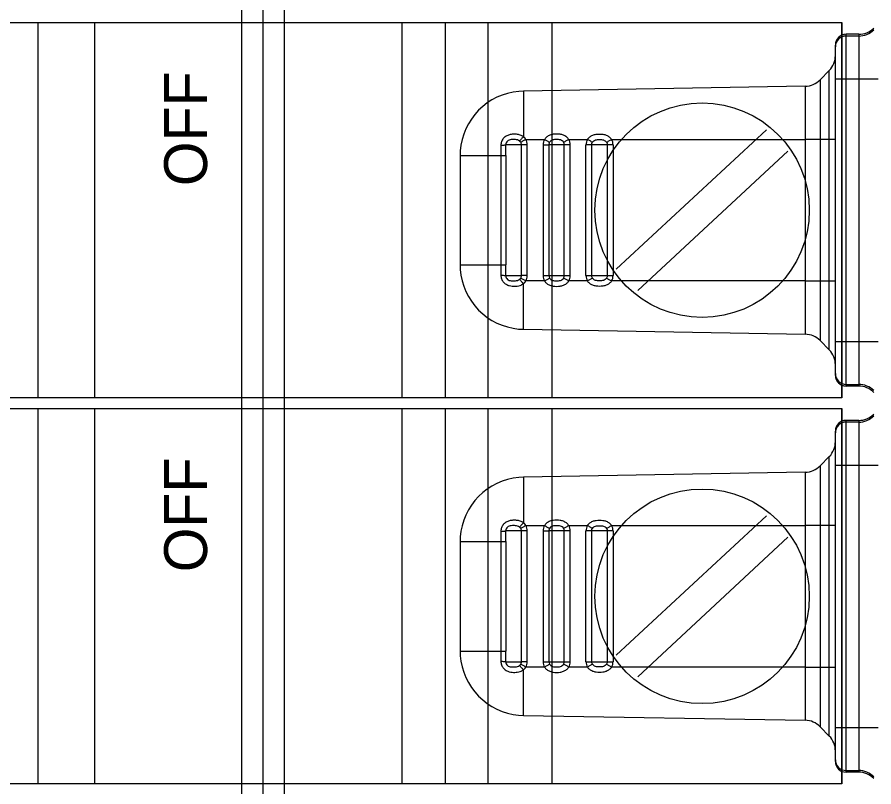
# Model space of a CAD drawing. Extents: x 0 to 4205, y 0 to 2970.
# Drawn here: x 958.55 to 998.5, y 1101.46 to 1137.34 of the extents above; entities that cross this region are included whole.
import ezdxf

# ---------------------------------------------------------------- set-up
doc = ezdxf.new("R2010")
doc.units = 0
doc.layers.add('Level 1', color=7, linetype='Continuous')

# ---------------------------------------------------------------- blocks, each defined once
blk = doc.blocks.new('NCX-2418-3U')
for p, q in [((-178, 132.85), (-178, -99.15)), ((-177, 132.85), (-177, -99.15)), ((-176, 132.85), (-176, -99.15)), ((-149.8, 53.451), (-149.8, 69.849)), ((-149.214, 69.849), (-149.8, 69.849)), ((-149.214, 69.849), (-149.8, 69.849)), ((-149.214, 69.77), (-149.8, 69.77)), ((-149.214, 69.849), (-149.214, 53.451)), ((-150.3, 53.951), (-150.3, 69.349)), ((-150.587, 68.164), (-151.013, 67.73)), ((-150.587, 55.136), (-150.587, 68.164)), ((-151.013, 67.73), (-151.013, 55.57)), ((-150.3, 67.771), (-148.3, 67.771)), ((-151.709, 67.431), (-164.852, 67.201)), ((-164.852, 67.201), (-164.852, 65.074)), ((-151.709, 67.431), (-151.709, 64.95)), ((-164.735, 64.95), (-163.865, 64.95)), ((-162.735, 64.95), (-161.865, 64.95)), ((-160.735, 64.95), (-151.709, 64.95)), ((-151.709, 64.95), (-151.709, 55.869)), ((-150.3, 64.95), (-151.709, 64.95)), ((-164.668, 64.7), (-165.674, 64.7)), ((-164.942, 58.6), (-164.942, 64.7)), ((-164.668, 58.6), (-164.668, 64.7)), ((-163.932, 64.7), (-163.932, 58.6)), ((-163.932, 64.7), (-163.664, 64.7)), ((-163.664, 64.7), (-163.664, 58.6)), ((-162.942, 64.7), (-163.664, 64.7)), ((-162.942, 58.6), (-162.942, 64.7)), ((-162.668, 64.7), (-162.942, 64.7)), ((-162.668, 58.6), (-162.668, 64.7)), ((-161.932, 58.6), (-161.932, 64.7)), ((-160.668, 64.7), (-161.932, 64.7)), ((-161.664, 58.6), (-161.664, 64.7)), ((-160.942, 64.7), (-160.942, 58.6)), ((-160.668, 64.7), (-160.668, 58.6)), ((-167.8, 64.202), (-167.8, 59.098)), ((-167.8, 64.202), (-165.67, 64.202)), ((-165.902, 64.202), (-165.902, 59.098)), ((-165.67, 64.202), (-165.67, 59.098)), ((-167.8, 59.098), (-165.902, 59.098)), ((-165.902, 59.098), (-165.67, 59.098)), ((-165.674, 58.6), (-164.942, 58.6)), ((-164.668, 58.6), (-164.942, 58.6)), ((-163.865, 58.35), (-164.735, 58.35)), ((-163.932, 58.6), (-162.668, 58.6)), ((-161.865, 58.35), (-162.735, 58.35)), ((-161.932, 58.6), (-160.668, 58.6)), ((-151.709, 58.35), (-160.735, 58.35)), ((-151.709, 58.35), (-150.3, 58.35)), ((-164.852, 56.099), (-164.852, 58.225)), ((-164.852, 56.099), (-151.709, 55.869)), ((-151.013, 55.57), (-150.587, 55.136)), ((-150.3, 55.529), (-148.3, 55.529)), ((-149.8, 53.53), (-149.214, 53.53)), ((-149.214, 53.451), (-149.8, 53.451)), ((-149.214, 53.451), (-149.8, 53.451)), ((-149.8, 35.451), (-149.8, 51.849)), ((-149.214, 51.849), (-149.8, 51.849)), ((-149.214, 51.849), (-149.8, 51.849)), ((-149.214, 51.77), (-149.8, 51.77)), ((-149.214, 51.849), (-149.214, 35.451)), ((-150.3, 35.951), (-150.3, 51.349)), ((-150.587, 50.164), (-151.013, 49.73)), ((-150.587, 37.136), (-150.587, 50.164)), ((-151.013, 49.73), (-151.013, 37.57)), ((-150.3, 49.771), (-148.3, 49.771)), ((-151.709, 49.431), (-164.852, 49.201)), ((-164.852, 49.201), (-164.852, 47.074)), ((-151.709, 49.431), (-151.709, 37.869)), ((-164.735, 46.95), (-163.865, 46.95)), ((-162.735, 46.95), (-161.865, 46.95)), ((-160.735, 46.95), (-151.709, 46.95)), ((-150.3, 46.95), (-151.709, 46.95)), ((-164.668, 46.7), (-165.674, 46.7)), ((-164.942, 40.6), (-164.942, 46.7)), ((-164.668, 40.6), (-164.668, 46.7)), ((-163.932, 46.7), (-163.932, 40.6)), ((-163.932, 46.7), (-163.664, 46.7)), ((-163.664, 46.7), (-163.664, 40.6)), ((-162.942, 46.7), (-163.664, 46.7)), ((-162.942, 40.6), (-162.942, 46.7)), ((-162.668, 46.7), (-162.942, 46.7)), ((-162.668, 40.6), (-162.668, 46.7)), ((-161.932, 40.6), (-161.932, 46.7)), ((-160.668, 46.7), (-161.932, 46.7)), ((-161.664, 40.6), (-161.664, 46.7)), ((-160.942, 46.7), (-160.942, 40.6)), ((-160.668, 46.7), (-160.668, 40.6)), ((-167.8, 46.202), (-167.8, 41.098)), ((-167.8, 46.202), (-165.67, 46.202)), ((-165.902, 46.202), (-165.902, 41.098)), ((-165.67, 46.202), (-165.67, 41.098)), ((-167.8, 41.098), (-165.902, 41.098)), ((-165.902, 41.098), (-165.67, 41.098)), ((-165.674, 40.6), (-164.942, 40.6)), ((-164.668, 40.6), (-164.942, 40.6)), ((-163.932, 40.6), (-162.668, 40.6)), ((-161.932, 40.6), (-160.668, 40.6)), ((-151.709, 40.35), (-150.3, 40.35)), ((-164.852, 38.099), (-164.852, 40.225)), ((-163.865, 40.35), (-164.735, 40.35)), ((-161.865, 40.35), (-162.735, 40.35)), ((-151.709, 40.35), (-160.735, 40.35)), ((-164.852, 38.099), (-151.709, 37.869)), ((-151.013, 37.57), (-150.587, 37.136)), ((-150.3, 37.529), (-148.3, 37.529)), ((-149.8, 35.53), (-149.214, 35.53)), ((-149.214, 35.451), (-149.8, 35.451)), ((-149.214, 35.451), (-149.8, 35.451))]:
    blk.add_line(p, q)
for points in [[(-164.852, 67.201), (-165.07, 67.19), (-165.331, 67.155), (-165.588, 67.096), (-165.84, 67.016), (-166.083, 66.914), (-166.316, 66.791), (-166.537, 66.648), (-166.746, 66.486), (-166.939, 66.306), (-167.115, 66.11), (-167.274, 65.899), (-167.413, 65.676), (-167.532, 65.44), (-167.631, 65.196), (-167.707, 64.943), (-167.761, 64.685), (-167.792, 64.423), (-167.8, 64.202)], [(-167.8, 59.098), (-167.792, 58.88), (-167.761, 58.619), (-167.708, 58.36), (-167.632, 58.108), (-167.534, 57.863), (-167.415, 57.628), (-167.276, 57.404), (-167.117, 57.193), (-166.941, 56.997), (-166.748, 56.817), (-166.541, 56.655), (-166.319, 56.511), (-166.086, 56.388), (-165.843, 56.285), (-165.592, 56.205), (-165.335, 56.146), (-165.073, 56.111), (-164.852, 56.099)], [(-164.852, 49.201), (-165.07, 49.19), (-165.331, 49.155), (-165.588, 49.096), (-165.84, 49.016), (-166.083, 48.914), (-166.316, 48.791), (-166.537, 48.648), (-166.746, 48.486), (-166.939, 48.306), (-167.115, 48.11), (-167.274, 47.899), (-167.413, 47.676), (-167.532, 47.44), (-167.631, 47.196), (-167.707, 46.943), (-167.761, 46.685), (-167.792, 46.423), (-167.8, 46.202)], [(-167.8, 41.098), (-167.792, 40.88), (-167.761, 40.619), (-167.708, 40.36), (-167.632, 40.108), (-167.534, 39.863), (-167.415, 39.628), (-167.276, 39.404), (-167.117, 39.193), (-166.941, 38.997), (-166.748, 38.817), (-166.541, 38.655), (-166.319, 38.511), (-166.086, 38.388), (-165.843, 38.285), (-165.592, 38.205), (-165.335, 38.146), (-165.073, 38.111), (-164.852, 38.099)]]:
    blk.add_lwpolyline(points)
for centre, radius, start, end in [((-149.214, 70.849), 1, 270, 315), ((-149.214, 70.849), 1, 269.9984, 314.9877), ((-149.214, 70.77), 1, 269.9984, 314.9877), ((-149.8, 69.349), 0.5, 90, 180), ((-149.8, 69.349), 0.5, 89.9895, 179.9895), ((-149.8, 69.27), 0.5, 89.9895, 179.9895), ((-151.3, 68.865), 1, 315.5, 359.9974), ((-151.726, 68.431), 1, 271, 315.4998), ((-165.167, 64.7), 0.499, 0.0299, 30.0713), ((-163.433, 64.7), 0.5, 149.9278, 179.963), ((-163.167, 64.7), 0.5, 0.0336, 30.0749), ((-161.433, 64.7), 0.499, 149.9288, 179.9703), ((-161.167, 64.7), 0.499, 0.0299, 30.0709), ((-194.009, 64.214), 28.339, 359.9754, 0.9825), ((-194.015, 59.086), 28.344, 359.0176, 0.0247), ((-165.167, 58.6), 0.499, 329.9312, 359.969), ((-163.433, 58.6), 0.5, 180.0364, 210.0773), ((-163.447, 58.6), 0.217, 180.0423, 211.5562), ((-163.167, 58.6), 0.499, 329.9303, 359.9687), ((-161.433, 58.6), 0.499, 180.0293, 210.0718), ((-161.167, 58.6), 0.499, 329.9282, 359.9708), ((-151.726, 54.869), 1, 44.5002, 89), ((-151.3, 54.435), 1, 0.0453, 44.5), ((-149.8, 54.03), 0.5, 180.0105, 270.0105), ((-149.8, 53.951), 0.5, 180, 270), ((-149.8, 53.951), 0.5, 180.0105, 270.0105), ((-149.214, 52.53), 1, 45.0123, 90.0016), ((-149.214, 52.451), 1, 45.0123, 90.0016), ((-149.214, 52.451), 1, 45, 90), ((-149.214, 52.849), 1, 270, 315), ((-149.214, 52.849), 1, 269.9984, 314.9877), ((-149.214, 52.77), 1, 269.9984, 314.9877), ((-149.8, 51.349), 0.5, 90, 180), ((-149.8, 51.349), 0.5, 89.9895, 179.9895), ((-149.8, 51.27), 0.5, 89.9895, 179.9895), ((-151.3, 50.865), 1, 315.5, 359.9974), ((-151.726, 50.431), 1, 271, 315.4998), ((-165.167, 46.7), 0.499, 0.0299, 30.0713), ((-163.433, 46.7), 0.5, 149.9278, 179.963), ((-163.167, 46.7), 0.5, 0.0336, 30.0749), ((-161.433, 46.7), 0.499, 149.9288, 179.9703), ((-161.167, 46.7), 0.499, 0.0299, 30.0709), ((-194.009, 46.214), 28.339, 359.9754, 0.9825), ((-194.015, 41.086), 28.344, 359.0176, 0.0247), ((-165.167, 40.6), 0.499, 329.9312, 359.969), ((-163.433, 40.6), 0.5, 180.0364, 210.0773), ((-163.447, 40.6), 0.217, 180.0423, 211.5562), ((-163.167, 40.6), 0.499, 329.9303, 359.9687), ((-161.433, 40.6), 0.499, 180.0293, 210.0718), ((-161.167, 40.6), 0.499, 329.9282, 359.9708), ((-151.726, 36.869), 1, 44.5002, 89), ((-151.3, 36.435), 1, 0.0453, 44.5), ((-149.8, 36.03), 0.5, 180.0105, 270.0105), ((-149.8, 35.951), 0.5, 180, 270), ((-149.8, 35.951), 0.5, 180.0105, 270.0105), ((-149.214, 34.53), 1, 45.0123, 90.0016), ((-149.214, 34.451), 1, 45.0123, 90.0016), ((-149.214, 34.451), 1, 45, 90)]:
    blk.add_arc(centre, radius, start, end)
for points, degree in [([(-164.852, 65.074), (-164.897, 65.109), (-164.998, 65.163), (-165.166, 65.197), (-165.336, 65.197), (-165.504, 65.174), (-165.663, 65.109), (-165.794, 64.997), (-165.88, 64.848), (-165.901, 64.734), (-165.901, 64.678)], 3), ([(-162.735, 64.95), (-162.764, 64.995), (-162.839, 65.075), (-162.981, 65.154), (-163.139, 65.194), (-163.3, 65.204), (-163.461, 65.194), (-163.618, 65.154), (-163.761, 65.075), (-163.836, 64.995), (-163.865, 64.95)], 3), ([(-161.865, 64.95), (-161.836, 64.995), (-161.761, 65.075), (-161.619, 65.155), (-161.461, 65.194), (-161.3, 65.204), (-161.138, 65.194), (-160.981, 65.155), (-160.839, 65.075), (-160.764, 64.995), (-160.735, 64.95)], 3), ([(-165.031, 64.878), (-165.057, 64.898), (-165.119, 64.928), (-165.217, 64.942), (-165.316, 64.945), (-165.414, 64.942), (-165.511, 64.927), (-165.6, 64.881), (-165.662, 64.801), (-165.676, 64.733), (-165.674, 64.7)], 3), ([(-164.852, 65.074), (-164.887, 65.034), (-164.935, 64.978), (-164.996, 64.913), (-165.021, 64.888), (-165.031, 64.878)], 3), ([(-164.974, 64.814), (-164.989, 64.838), (-165.009, 64.86), (-165.031, 64.878)], 2), ([(-164.735, 64.95), (-164.782, 64.923), (-164.861, 64.877), (-164.941, 64.832), (-164.974, 64.814)], 3), ([(-164.942, 64.7), (-164.942, 64.72), (-164.947, 64.76), (-164.964, 64.797), (-164.974, 64.814)], 3), ([(-164.735, 64.95), (-164.766, 64.998), (-164.807, 65.04), (-164.852, 65.074)], 2), ([(-163.865, 64.95), (-163.819, 64.923), (-163.741, 64.878), (-163.663, 64.832), (-163.632, 64.814)], 3), ([(-163.632, 64.814), (-163.643, 64.797), (-163.659, 64.76), (-163.664, 64.72), (-163.664, 64.7)], 3), ([(-162.974, 64.814), (-162.99, 64.84), (-163.033, 64.887), (-163.119, 64.927), (-163.211, 64.941), (-163.304, 64.943), (-163.396, 64.941), (-163.488, 64.927), (-163.573, 64.887), (-163.616, 64.84), (-163.632, 64.814)], 3), ([(-162.735, 64.95), (-162.782, 64.923), (-162.861, 64.877), (-162.941, 64.832), (-162.974, 64.814)], 3), ([(-162.942, 64.7), (-162.942, 64.72), (-162.947, 64.76), (-162.964, 64.797), (-162.974, 64.814)], 3), ([(-161.632, 64.814), (-161.663, 64.832), (-161.741, 64.878), (-161.819, 64.923), (-161.865, 64.95)], 3), ([(-161.664, 64.7), (-161.664, 64.739), (-161.653, 64.78), (-161.632, 64.814)], 2), ([(-161.632, 64.814), (-161.616, 64.84), (-161.573, 64.887), (-161.488, 64.927), (-161.396, 64.941), (-161.304, 64.943), (-161.211, 64.941), (-161.119, 64.927), (-161.033, 64.887), (-160.99, 64.84), (-160.974, 64.814)], 3), ([(-160.974, 64.814), (-160.941, 64.832), (-160.861, 64.877), (-160.782, 64.923), (-160.735, 64.95)], 3), ([(-160.974, 64.814), (-160.964, 64.797), (-160.947, 64.76), (-160.942, 64.72), (-160.942, 64.7)], 3), ([(-165.901, 64.678), (-165.901, 64.519), (-165.902, 64.361), (-165.902, 64.202)], 2), ([(-165.901, 64.678), (-165.854, 64.68), (-165.791, 64.684), (-165.716, 64.692), (-165.686, 64.697), (-165.674, 64.7)], 3), ([(-165.902, 59.098), (-165.902, 58.94), (-165.901, 58.781), (-165.901, 58.622)], 2), ([(-165.901, 58.622), (-165.854, 58.62), (-165.791, 58.616), (-165.716, 58.608), (-165.686, 58.603), (-165.674, 58.6)], 3), ([(-165.901, 58.622), (-165.901, 58.566), (-165.88, 58.452), (-165.794, 58.303), (-165.663, 58.191), (-165.504, 58.126), (-165.364, 58.106), (-165.251, 58.103), (-165.138, 58.109), (-164.998, 58.137), (-164.897, 58.191), (-164.852, 58.225)], 3), ([(-165.674, 58.6), (-165.676, 58.567), (-165.662, 58.499), (-165.6, 58.419), (-165.511, 58.373), (-165.414, 58.358), (-165.316, 58.355), (-165.217, 58.358), (-165.119, 58.372), (-165.058, 58.402), (-165.031, 58.422)], 3), ([(-165.031, 58.422), (-165.009, 58.44), (-164.989, 58.462), (-164.974, 58.486)], 2), ([(-164.852, 58.225), (-164.887, 58.266), (-164.935, 58.322), (-164.996, 58.387), (-165.021, 58.412), (-165.031, 58.422)], 3), ([(-164.974, 58.486), (-164.964, 58.503), (-164.947, 58.54), (-164.942, 58.58), (-164.942, 58.6)], 3), ([(-164.735, 58.35), (-164.782, 58.377), (-164.861, 58.423), (-164.941, 58.468), (-164.974, 58.486)], 3), ([(-164.852, 58.225), (-164.807, 58.26), (-164.766, 58.302), (-164.735, 58.35)], 2), ([(-163.865, 58.35), (-163.819, 58.377), (-163.741, 58.422), (-163.663, 58.468), (-163.632, 58.486)], 3), ([(-163.865, 58.35), (-163.836, 58.305), (-163.761, 58.225), (-163.618, 58.146), (-163.461, 58.106), (-163.3, 58.096), (-163.138, 58.106), (-162.981, 58.146), (-162.839, 58.225), (-162.764, 58.305), (-162.735, 58.35)], 3), ([(-163.632, 58.486), (-163.616, 58.46), (-163.573, 58.413), (-163.488, 58.373), (-163.396, 58.359), (-163.304, 58.357), (-163.211, 58.359), (-163.119, 58.373), (-163.033, 58.413), (-162.99, 58.46), (-162.974, 58.486)], 3), ([(-162.974, 58.486), (-162.964, 58.503), (-162.947, 58.54), (-162.942, 58.58), (-162.942, 58.6)], 3), ([(-162.735, 58.35), (-162.782, 58.377), (-162.861, 58.423), (-162.941, 58.468), (-162.974, 58.486)], 3), ([(-161.632, 58.486), (-161.663, 58.468), (-161.741, 58.422), (-161.819, 58.377), (-161.865, 58.35)], 3), ([(-160.735, 58.35), (-160.764, 58.305), (-160.839, 58.225), (-160.981, 58.145), (-161.138, 58.106), (-161.3, 58.096), (-161.461, 58.106), (-161.619, 58.145), (-161.761, 58.225), (-161.836, 58.305), (-161.865, 58.35)], 3), ([(-161.632, 58.486), (-161.643, 58.503), (-161.659, 58.54), (-161.664, 58.58), (-161.664, 58.6)], 3), ([(-160.974, 58.486), (-160.99, 58.46), (-161.033, 58.413), (-161.119, 58.373), (-161.211, 58.359), (-161.304, 58.357), (-161.396, 58.359), (-161.488, 58.373), (-161.573, 58.413), (-161.616, 58.46), (-161.632, 58.486)], 3), ([(-160.942, 58.6), (-160.942, 58.58), (-160.947, 58.54), (-160.964, 58.503), (-160.974, 58.486)], 3), ([(-160.974, 58.486), (-160.941, 58.468), (-160.861, 58.423), (-160.782, 58.377), (-160.735, 58.35)], 3), ([(-164.852, 47.074), (-164.897, 47.109), (-164.998, 47.163), (-165.166, 47.197), (-165.336, 47.197), (-165.504, 47.174), (-165.663, 47.109), (-165.794, 46.997), (-165.88, 46.848), (-165.901, 46.734), (-165.901, 46.678)], 3), ([(-162.735, 46.95), (-162.764, 46.995), (-162.839, 47.075), (-162.981, 47.154), (-163.139, 47.194), (-163.3, 47.204), (-163.461, 47.194), (-163.618, 47.154), (-163.761, 47.075), (-163.836, 46.995), (-163.865, 46.95)], 3), ([(-161.865, 46.95), (-161.836, 46.995), (-161.761, 47.075), (-161.619, 47.155), (-161.461, 47.194), (-161.3, 47.204), (-161.138, 47.194), (-160.981, 47.155), (-160.839, 47.075), (-160.764, 46.995), (-160.735, 46.95)], 3), ([(-165.031, 46.878), (-165.057, 46.898), (-165.119, 46.928), (-165.217, 46.942), (-165.316, 46.945), (-165.414, 46.942), (-165.511, 46.927), (-165.6, 46.881), (-165.662, 46.801), (-165.676, 46.733), (-165.674, 46.7)], 3), ([(-164.852, 47.074), (-164.887, 47.034), (-164.935, 46.978), (-164.996, 46.913), (-165.021, 46.888), (-165.031, 46.878)], 3), ([(-164.974, 46.814), (-164.989, 46.838), (-165.009, 46.86), (-165.031, 46.878)], 2), ([(-164.735, 46.95), (-164.782, 46.923), (-164.861, 46.877), (-164.941, 46.832), (-164.974, 46.814)], 3), ([(-164.942, 46.7), (-164.942, 46.72), (-164.947, 46.76), (-164.964, 46.797), (-164.974, 46.814)], 3), ([(-164.735, 46.95), (-164.766, 46.998), (-164.807, 47.04), (-164.852, 47.074)], 2), ([(-163.865, 46.95), (-163.819, 46.923), (-163.741, 46.878), (-163.663, 46.832), (-163.632, 46.814)], 3), ([(-163.632, 46.814), (-163.643, 46.797), (-163.659, 46.76), (-163.664, 46.72), (-163.664, 46.7)], 3), ([(-162.974, 46.814), (-162.99, 46.84), (-163.033, 46.887), (-163.119, 46.927), (-163.211, 46.941), (-163.304, 46.943), (-163.396, 46.941), (-163.488, 46.927), (-163.573, 46.887), (-163.616, 46.84), (-163.632, 46.814)], 3), ([(-162.735, 46.95), (-162.782, 46.923), (-162.861, 46.877), (-162.941, 46.832), (-162.974, 46.814)], 3), ([(-162.942, 46.7), (-162.942, 46.72), (-162.947, 46.76), (-162.964, 46.797), (-162.974, 46.814)], 3), ([(-161.632, 46.814), (-161.663, 46.832), (-161.741, 46.878), (-161.819, 46.923), (-161.865, 46.95)], 3), ([(-161.664, 46.7), (-161.664, 46.739), (-161.653, 46.78), (-161.632, 46.814)], 2), ([(-161.632, 46.814), (-161.616, 46.84), (-161.573, 46.887), (-161.488, 46.927), (-161.396, 46.941), (-161.304, 46.943), (-161.211, 46.941), (-161.119, 46.927), (-161.033, 46.887), (-160.99, 46.84), (-160.974, 46.814)], 3), ([(-160.974, 46.814), (-160.941, 46.832), (-160.861, 46.877), (-160.782, 46.923), (-160.735, 46.95)], 3), ([(-160.974, 46.814), (-160.964, 46.797), (-160.947, 46.76), (-160.942, 46.72), (-160.942, 46.7)], 3), ([(-165.901, 46.678), (-165.901, 46.519), (-165.902, 46.361), (-165.902, 46.202)], 2), ([(-165.901, 46.678), (-165.854, 46.68), (-165.791, 46.684), (-165.716, 46.692), (-165.686, 46.697), (-165.674, 46.7)], 3), ([(-165.902, 41.098), (-165.902, 40.94), (-165.901, 40.781), (-165.901, 40.622)], 2), ([(-165.901, 40.622), (-165.854, 40.62), (-165.791, 40.616), (-165.716, 40.608), (-165.686, 40.603), (-165.674, 40.6)], 3), ([(-165.901, 40.622), (-165.901, 40.566), (-165.88, 40.452), (-165.794, 40.303), (-165.663, 40.191), (-165.504, 40.126), (-165.364, 40.106), (-165.251, 40.103), (-165.138, 40.109), (-164.998, 40.137), (-164.897, 40.191), (-164.852, 40.225)], 3), ([(-165.674, 40.6), (-165.676, 40.567), (-165.662, 40.499), (-165.6, 40.419), (-165.511, 40.373), (-165.414, 40.358), (-165.316, 40.355), (-165.217, 40.358), (-165.119, 40.372), (-165.058, 40.402), (-165.031, 40.422)], 3), ([(-165.031, 40.422), (-165.009, 40.44), (-164.989, 40.462), (-164.974, 40.486)], 2), ([(-164.852, 40.225), (-164.887, 40.266), (-164.935, 40.322), (-164.996, 40.387), (-165.021, 40.412), (-165.031, 40.422)], 3), ([(-164.974, 40.486), (-164.964, 40.503), (-164.947, 40.54), (-164.942, 40.58), (-164.942, 40.6)], 3), ([(-164.735, 40.35), (-164.782, 40.377), (-164.861, 40.423), (-164.941, 40.468), (-164.974, 40.486)], 3), ([(-163.865, 40.35), (-163.819, 40.377), (-163.741, 40.422), (-163.663, 40.468), (-163.632, 40.486)], 3), ([(-163.632, 40.486), (-163.616, 40.46), (-163.573, 40.413), (-163.488, 40.373), (-163.396, 40.359), (-163.304, 40.357), (-163.211, 40.359), (-163.119, 40.373), (-163.033, 40.413), (-162.99, 40.46), (-162.974, 40.486)], 3), ([(-162.974, 40.486), (-162.964, 40.503), (-162.947, 40.54), (-162.942, 40.58), (-162.942, 40.6)], 3), ([(-162.735, 40.35), (-162.782, 40.377), (-162.861, 40.423), (-162.941, 40.468), (-162.974, 40.486)], 3), ([(-161.632, 40.486), (-161.663, 40.468), (-161.741, 40.422), (-161.819, 40.377), (-161.865, 40.35)], 3), ([(-161.632, 40.486), (-161.643, 40.503), (-161.659, 40.54), (-161.664, 40.58), (-161.664, 40.6)], 3), ([(-160.974, 40.486), (-160.99, 40.46), (-161.033, 40.413), (-161.119, 40.373), (-161.211, 40.359), (-161.304, 40.357), (-161.396, 40.359), (-161.488, 40.373), (-161.573, 40.413), (-161.616, 40.46), (-161.632, 40.486)], 3), ([(-160.942, 40.6), (-160.942, 40.58), (-160.947, 40.54), (-160.964, 40.503), (-160.974, 40.486)], 3), ([(-160.974, 40.486), (-160.941, 40.468), (-160.861, 40.423), (-160.782, 40.377), (-160.735, 40.35)], 3), ([(-164.852, 40.225), (-164.807, 40.26), (-164.766, 40.302), (-164.735, 40.35)], 2), ([(-163.865, 40.35), (-163.836, 40.305), (-163.761, 40.225), (-163.618, 40.146), (-163.461, 40.106), (-163.3, 40.096), (-163.138, 40.106), (-162.981, 40.146), (-162.839, 40.225), (-162.764, 40.305), (-162.735, 40.35)], 3), ([(-160.735, 40.35), (-160.764, 40.305), (-160.839, 40.225), (-160.981, 40.145), (-161.138, 40.106), (-161.3, 40.096), (-161.461, 40.106), (-161.619, 40.145), (-161.761, 40.225), (-161.836, 40.305), (-161.865, 40.35)], 3)]:
    blk.add_open_spline(points, degree=degree)

msp = doc.modelspace()

# ---------------------------------------------------------------- linework, layer by layer
at = {"layer": 'Level 1'}
for p, q in [((914.008, 1137.093), (997.008, 1137.093)), ((959.508, 1137.093), (959.508, 1119.593)), ((962.161, 1137.093), (962.161, 1119.593)), ((976.508, 1119.593), (976.508, 1137.093)), ((978.508, 1137.093), (978.508, 1119.593)), ((980.508, 1119.593), (980.508, 1137.093)), ((983.49, 1137.093), (983.49, 1119.593)), ((997.008, 1119.593), (997.008, 1137.093)), ((993.49, 1132.093), (986.49, 1125.593)), ((987.49, 1124.593), (994.49, 1131.093)), ((997.008, 1119.593), (914.008, 1119.593)), ((914.008, 1119.093), (997.008, 1119.093)), ((959.508, 1119.093), (959.508, 1101.593)), ((962.161, 1119.093), (962.161, 1101.593)), ((976.508, 1101.593), (976.508, 1119.093)), ((978.508, 1119.093), (978.508, 1101.593)), ((980.508, 1101.593), (980.508, 1119.093)), ((983.49, 1119.093), (983.49, 1101.593)), ((997.008, 1101.593), (997.008, 1119.093)), ((993.49, 1114.093), (986.49, 1107.593)), ((987.49, 1106.593), (994.49, 1113.093)), ((997.008, 1101.593), (914.008, 1101.593))]:
    msp.add_line(p, q, dxfattribs=at)
for points in [[(914.008, 1119.593), (914.008, 1137.093), (997.008, 1137.093), (997.008, 1119.593)], [(914.008, 1119.593), (914.008, 1137.093), (997.008, 1137.093), (997.008, 1119.593)], [(914.008, 1101.593), (914.008, 1119.093), (997.008, 1119.093), (997.008, 1101.593)], [(914.008, 1101.593), (914.008, 1119.093), (997.008, 1119.093), (997.008, 1101.593)]]:
    msp.add_lwpolyline(points, close=True, dxfattribs=at)
for centre in [(990.49, 1128.343), (990.49, 1110.343)]:
    msp.add_circle(centre, 5, dxfattribs=at)

# ---------------------------------------------------------------- block references
msp.add_blockref('NCX-2418-3U', (1147.008, 1066.693))

# ---------------------------------------------------------------- texts
for p in [(967.406, 1129.466), (967.406, 1111.466)]:
    msp.add_text('OFF', height=2, rotation=90, dxfattribs=at).set_placement(p)

doc.saveas('drawing.dxf')
